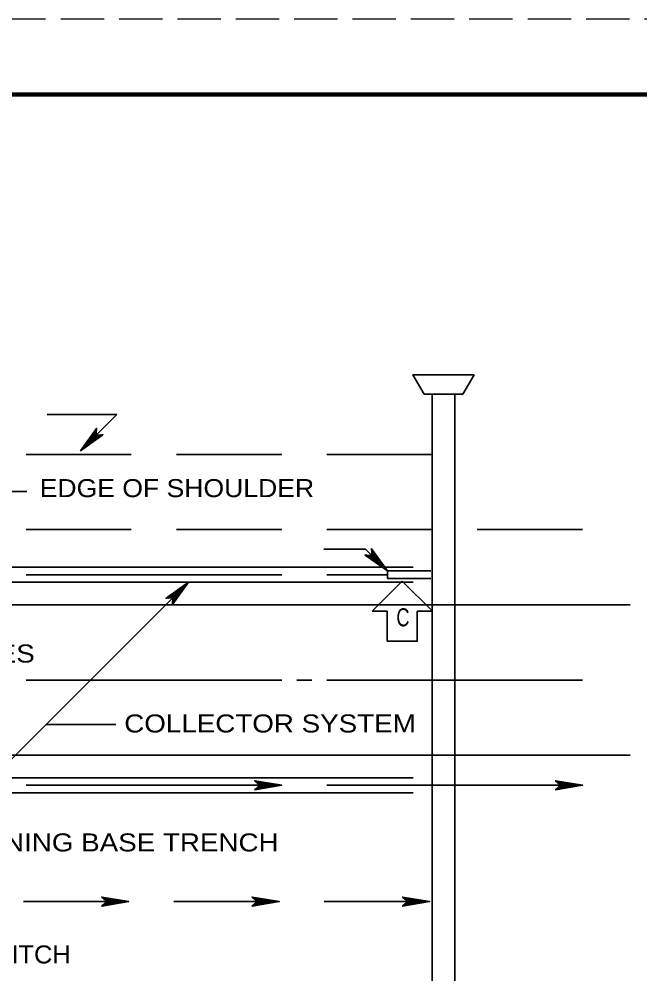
# Model space of a CAD drawing. Extents: x -48732 to -48696.6, y -117659.8 to -117637.8.
# Drawn here: x -48721.38 to -48717.26, y -117644.24 to -117637.85 of the extents above; entities that cross this region are included whole.
import ezdxf

# ---------------------------------------------------------------- set-up
doc = ezdxf.new("R2010")
doc.units = 0
doc.header["$LTSCALE"] = 0.048
doc.linetypes.add('LONG_DASHED', pattern=[7.5, 6, -1.5])
doc.layers.add('1', color=7, linetype='Continuous', lineweight=25)
doc.layers.add('3', color=7, linetype='Continuous', lineweight=35)

msp = doc.modelspace()

# ---------------------------------------------------------------- linework, layer by layer
at = {"layer": '1', "linetype": 'LONG_DASHED'}
msp.add_line((-48696.76492, -117637.84817), (-48731.96492, -117637.84817), dxfattribs=at)
at = {"layer": '1', "lineweight": 158}
msp.add_line((-48696.84825, -117638.34817), (-48729.34825, -117638.34817), dxfattribs=at)
at = {"layer": '3'}
for p, q in [((-48718.63958, -117644.24217), (-48718.63958, -117640.34217)), ((-48718.48958, -117644.24217), (-48718.48958, -117640.34217)), ((-48721.19958, -117640.47717), (-48720.73658, -117640.47717)), ((-48720.97658, -117640.71717), (-48720.73658, -117640.47717)), ((-48721.33958, -117640.74217), (-48720.63958, -117640.74217)), ((-48720.33958, -117640.74217), (-48719.63958, -117640.74217)), ((-48719.33958, -117640.74217), (-48718.63958, -117640.74217)), ((-48722.03458, -117640.98917), (-48721.33458, -117640.98917)), ((-48721.33958, -117641.24217), (-48720.63958, -117641.24217)), ((-48720.33958, -117641.24217), (-48719.63958, -117641.24217)), ((-48719.33958, -117641.24217), (-48718.63958, -117641.24217)), ((-48718.33958, -117641.24217), (-48717.63958, -117641.24217)), ((-48719.36058, -117641.37317), (-48719.08258, -117641.37317)), ((-48718.93758, -117641.51717), (-48719.08258, -117641.37317)), ((-48727.33958, -117641.49217), (-48718.76717, -117641.49217)), ((-48721.33958, -117641.54217), (-48719.63958, -117641.54217)), ((-48719.33958, -117641.54217), (-48718.93758, -117641.54217)), ((-48718.93758, -117641.51717), (-48718.93758, -117641.56717)), ((-48727.33958, -117641.59217), (-48718.76717, -117641.59217)), ((-48721.5605, -117642.89217), (-48720.2605, -117641.59217)), ((-48719.03858, -117641.78417), (-48718.83858, -117641.58417)), ((-48718.63858, -117641.78417), (-48718.83858, -117641.58417)), ((-48727.33958, -117641.74217), (-48717.32258, -117641.74217)), ((-48719.03858, -117641.78417), (-48718.93858, -117641.78417)), ((-48718.93858, -117641.98417), (-48718.93858, -117641.78417)), ((-48718.73858, -117641.78417), (-48718.63858, -117641.78417)), ((-48721.33958, -117642.24217), (-48719.63958, -117642.24217)), ((-48719.43958, -117642.24217), (-48719.53958, -117642.24217)), ((-48719.33958, -117642.24217), (-48717.63958, -117642.24217)), ((-48721.20567, -117642.53733), (-48720.74267, -117642.53733)), ((-48727.33958, -117642.74217), (-48717.32258, -117642.74217)), ((-48727.43958, -117642.89217), (-48718.76717, -117642.89217)), ((-48721.33958, -117642.94217), (-48719.63958, -117642.94217)), ((-48719.33958, -117642.94217), (-48717.63958, -117642.94217)), ((-48727.43958, -117642.99217), (-48718.76717, -117642.99217)), ((-48721.35658, -117643.71517), (-48720.65658, -117643.71517)), ((-48720.35658, -117643.71517), (-48719.65658, -117643.71517)), ((-48719.35658, -117643.71517), (-48718.65658, -117643.71517))]:
    msp.add_line(p, q, dxfattribs=at)
at = {"layer": '3', "linetype": 'LONG_DASHED'}
for p, q in [((-48718.93758, -117641.51717), (-48718.63958, -117641.51717)), ((-48718.93758, -117641.56717), (-48718.63958, -117641.56717))]:
    msp.add_line(p, q, dxfattribs=at)
at = {"layer": '3'}
for points in [[(-48718.69258, -117640.34217), (-48718.76758, -117640.21217), (-48718.36158, -117640.21217)], [(-48718.69258, -117640.34217), (-48718.43658, -117640.34217), (-48718.36158, -117640.21217)], [(-48720.87058, -117640.56917), (-48720.97658, -117640.71717), (-48720.82858, -117640.61117), (-48720.83358, -117640.61117), (-48720.96358, -117640.70417), (-48720.87058, -117640.57417), (-48720.87158, -117640.58017), (-48720.95058, -117640.69117), (-48720.83958, -117640.61217), (-48720.84558, -117640.61317), (-48720.93758, -117640.67817), (-48720.87258, -117640.58617), (-48720.87258, -117640.59217), (-48720.92458, -117640.66517), (-48720.85158, -117640.61317), (-48720.85758, -117640.61417), (-48720.91258, -117640.65317), (-48720.87358, -117640.59817), (-48720.87358, -117640.60417), (-48720.89958, -117640.64017), (-48720.86358, -117640.61417), (-48720.86958, -117640.61517), (-48720.88658, -117640.62717), (-48720.87458, -117640.61017), (-48720.87058, -117640.56917), (-48720.87458, -117640.61517), (-48720.82858, -117640.61117)], [(-48719.08558, -117641.41117), (-48718.93758, -117641.51717), (-48719.04358, -117641.36917), (-48719.04358, -117641.37417), (-48718.95058, -117641.50417), (-48719.08058, -117641.41117), (-48719.07458, -117641.41217), (-48718.96358, -117641.49117), (-48719.04258, -117641.38017), (-48719.04158, -117641.38617), (-48718.97658, -117641.47817), (-48719.06858, -117641.41317), (-48719.06258, -117641.41317), (-48718.98958, -117641.46517), (-48719.04158, -117641.39217), (-48719.04058, -117641.39817), (-48719.00158, -117641.45317), (-48719.05658, -117641.41417), (-48719.05058, -117641.41417), (-48719.01458, -117641.44017), (-48719.04058, -117641.40417), (-48719.03958, -117641.41017), (-48719.02758, -117641.42717), (-48719.04458, -117641.41517), (-48719.08558, -117641.41117), (-48719.03958, -117641.41517), (-48719.04358, -117641.36917)], [(-48720.3665, -117641.74017), (-48720.2605, -117641.59217), (-48720.4085, -117641.69817), (-48720.4035, -117641.69817), (-48720.2735, -117641.60517), (-48720.3665, -117641.73517), (-48720.3655, -117641.72917), (-48720.2865, -117641.61817), (-48720.3975, -117641.69717), (-48720.3915, -117641.69617), (-48720.2995, -117641.63117), (-48720.3645, -117641.72317), (-48720.3645, -117641.71717), (-48720.3125, -117641.64417), (-48720.3855, -117641.69617), (-48720.3795, -117641.69517), (-48720.3245, -117641.65617), (-48720.3635, -117641.71117), (-48720.3635, -117641.70517), (-48720.3375, -117641.66917), (-48720.3735, -117641.69517), (-48720.3675, -117641.69417), (-48720.3505, -117641.68217), (-48720.3625, -117641.69917), (-48720.3665, -117641.74017), (-48720.3625, -117641.69417), (-48720.4085, -117641.69817)], [(-48718.93858, -117641.98417), (-48718.73858, -117641.98417), (-48718.73858, -117641.78417)], [(-48719.81958, -117642.97217), (-48719.63958, -117642.94217), (-48719.81958, -117642.91217), (-48719.81458, -117642.91617), (-48719.65758, -117642.94217), (-48719.81558, -117642.96817), (-48719.81058, -117642.96417), (-48719.67658, -117642.94217), (-48719.81058, -117642.92017), (-48719.80558, -117642.92317), (-48719.69458, -117642.94217), (-48719.80558, -117642.96117), (-48719.80158, -117642.95717), (-48719.71258, -117642.94217), (-48719.80158, -117642.92717), (-48719.79658, -117642.93117), (-48719.73058, -117642.94217), (-48719.79658, -117642.95317), (-48719.79258, -117642.94917), (-48719.74958, -117642.94217), (-48719.79258, -117642.93517), (-48719.78758, -117642.93917), (-48719.76758, -117642.94217), (-48719.78758, -117642.94517), (-48719.81958, -117642.97217), (-48719.78358, -117642.94217), (-48719.81958, -117642.91217)], [(-48717.81958, -117642.97217), (-48717.63958, -117642.94217), (-48717.81958, -117642.91217), (-48717.81458, -117642.91617), (-48717.65758, -117642.94217), (-48717.81558, -117642.96817), (-48717.81058, -117642.96417), (-48717.67658, -117642.94217), (-48717.81058, -117642.92017), (-48717.80558, -117642.92317), (-48717.69458, -117642.94217), (-48717.80558, -117642.96117), (-48717.80158, -117642.95717), (-48717.71258, -117642.94217), (-48717.80158, -117642.92717), (-48717.79658, -117642.93117), (-48717.73058, -117642.94217), (-48717.79658, -117642.95317), (-48717.79258, -117642.94917), (-48717.74958, -117642.94217), (-48717.79258, -117642.93517), (-48717.78758, -117642.93917), (-48717.76758, -117642.94217), (-48717.78758, -117642.94517), (-48717.81958, -117642.97217), (-48717.78358, -117642.94217), (-48717.81958, -117642.91217)], [(-48720.83658, -117643.74517), (-48720.65658, -117643.71517), (-48720.83658, -117643.68517), (-48720.83158, -117643.68917), (-48720.67458, -117643.71517), (-48720.83258, -117643.74117), (-48720.82758, -117643.73717), (-48720.69358, -117643.71517), (-48720.82758, -117643.69317), (-48720.82258, -117643.69617), (-48720.71158, -117643.71517), (-48720.82258, -117643.73417), (-48720.81858, -117643.73017), (-48720.72958, -117643.71517), (-48720.81858, -117643.70017), (-48720.81358, -117643.70417), (-48720.74758, -117643.71517), (-48720.81358, -117643.72617), (-48720.80958, -117643.72217), (-48720.76658, -117643.71517), (-48720.80958, -117643.70817), (-48720.80458, -117643.71217), (-48720.78458, -117643.71517), (-48720.80458, -117643.71817), (-48720.83658, -117643.74517), (-48720.80058, -117643.71517), (-48720.83658, -117643.68517)], [(-48719.83658, -117643.74517), (-48719.65658, -117643.71517), (-48719.83658, -117643.68517), (-48719.83158, -117643.68917), (-48719.67458, -117643.71517), (-48719.83258, -117643.74117), (-48719.82758, -117643.73717), (-48719.69358, -117643.71517), (-48719.82758, -117643.69317), (-48719.82258, -117643.69617), (-48719.71158, -117643.71517), (-48719.82258, -117643.73417), (-48719.81858, -117643.73017), (-48719.72958, -117643.71517), (-48719.81858, -117643.70017), (-48719.81358, -117643.70417), (-48719.74758, -117643.71517), (-48719.81358, -117643.72617), (-48719.80958, -117643.72217), (-48719.76658, -117643.71517), (-48719.80958, -117643.70817), (-48719.80458, -117643.71217), (-48719.78458, -117643.71517), (-48719.80458, -117643.71817), (-48719.83658, -117643.74517), (-48719.80058, -117643.71517), (-48719.83658, -117643.68517)], [(-48718.83658, -117643.74517), (-48718.65658, -117643.71517), (-48718.83658, -117643.68517), (-48718.83158, -117643.68917), (-48718.67458, -117643.71517), (-48718.83258, -117643.74117), (-48718.82758, -117643.73717), (-48718.69358, -117643.71517), (-48718.82758, -117643.69317), (-48718.82258, -117643.69617), (-48718.71158, -117643.71517), (-48718.82258, -117643.73417), (-48718.81858, -117643.73017), (-48718.72958, -117643.71517), (-48718.81858, -117643.70017), (-48718.81358, -117643.70417), (-48718.74758, -117643.71517), (-48718.81358, -117643.72617), (-48718.80958, -117643.72217), (-48718.76658, -117643.71517), (-48718.80958, -117643.70817), (-48718.80458, -117643.71217), (-48718.78458, -117643.71517), (-48718.80458, -117643.71817), (-48718.83658, -117643.74517), (-48718.80058, -117643.71517), (-48718.83658, -117643.68517)]]:
    msp.add_lwpolyline(points, dxfattribs=at)

# ---------------------------------------------------------------- texts
for s, width, p in [('EDGE OF SHOULDER', 1.1, (-48721.24858, -117641.02617)), ('C', 0.75, (-48718.87758, -117641.88517)), ('C TRAVELED LANES', 1.15, (-48723.09658, -117642.12617)), ('COLLECTOR SYSTEM', 1.15, (-48720.68658, -117642.59117)), ('FREE DRAINING BASE TRENCH', 1.15, (-48722.46992, -117643.38225)), ('MEDIAN DITCH', 1.05, (-48722.25958, -117644.12717))]:
    msp.add_text(s, height=0.12, dxfattribs=dict(at, width=width)).set_placement(p)

doc.saveas('drawing.dxf')
